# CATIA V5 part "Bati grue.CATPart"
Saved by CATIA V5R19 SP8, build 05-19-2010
Part number: Bati grue
Bounding box of the stored display mesh (mm): x -155 to 155, y -1230 to 420, z -1340 to 60
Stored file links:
  G:\EU_thinkMotion\CFAO_2010\MMS_groupe3\MMS_groupe3\rdalborgo\rdalborgo\Bati grue.CATPart
  G:\EU_thinkMotion\CFAO_2010\MMS_groupe3\MMS_groupe3\rdalborgo\rdalborgo\rdalborgo.CATProduct
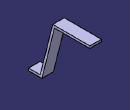
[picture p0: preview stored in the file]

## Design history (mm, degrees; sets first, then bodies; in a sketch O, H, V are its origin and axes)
External parameters (linked from other documents)
  External.entraxe = 500 mm
  `External.Largeur bielle` = 210 mm
Set1
  Plane1: linked copy from another document
  Point1 to Point3: linked copy from another document
  Plane2: linked copy from another document
  Plane3: linked copy from another document
Body1 (main body)
  Sketch1 on Plane1, origin (0, 0, 0), H (0, 1, 0), V (0, 0, 1)
    point P1 (-580, 60)
    line L1 (-580, 60) -> (420, 60)
    line L2 (420, 60) -> (420, 0)
    line L3 (420, 0) -> (-533.2139, 0)
    line L4 (-533.2139, 0) -> (-870, -1340)
    line L5 (-870, -1340) -> (-1230, -1340)
    line L6 (-1230, -1340) -> (-1230, -1280)
    line L7 (-1230, -1280) -> (-916.7861, -1280)
    line L8 (-916.7861, -1280) -> (-580, 60)
    point P9 (-580, 60)
    reference projected point E1 (320, 0) from Point1
    reference projected point E2 (320, 0) from Point1
    reference projected point E3 (-950, -1340) from Point3
    reference projected point E4 (-950, -1340) from Point3
    distance L3 L1 = 60
    distance L7 L5 = 60
    distance L8 L4 = 60
    distance L2 E1 = 100
    length L1 = 1000 {= External.entraxe +500mm}
    length L5 = 360
    distance L6 E4 = 280
    horizontal: L1 H, L3 H, L5 H, L7 H
    vertical: L2 V, L6 V
    coincidence: L3 E2, E3 L5, P1 P9
  Pad1: profile Sketch1, direction (1, 0, 0), length 155 {= `External.Largeur bielle` /2+50mm}, mirrored extent
  Sketch2 on face of Pad1 from Sketch1.L5, origin (-124.0653, -1194.0759, -1340), H (1, 0, 0), V (0, -1, 0)
    point P1 (174.0653, -64.0759)
    reference intersected line E1 through (124.0653, 0) direction (0, 1) from Plane1
    reference intersected line E2 through (0, -244.0759) direction (1, 0) from Plane2
    distance P1 E1 = 50
    distance P1 E2 = 180
  Hole1: placed by Sketch2, at (50, -1130, -1340) direction (0, 0, 1), diameter 10, depth 30
  RectPattern1: of Hole1, direction 1 instances 2, spacing 200, along face of Pad1 from Sketch1.L5 reversed, direction 2 instances 2, spacing 100, along face of Pad1 from Sketch1.L5
  Sketch3 on face of Pad1 from Sketch1.L3, origin (86.1973, -350.7932, 0), H (1, 0, 0), V (0, -1, 0)
    point P1 (-26.1973, -225.7932)
    reference intersected line E1 through (-86.1973, 0) direction (0, 1) from Plane1
    reference intersected line E2 through (0, -350.7932) direction (1, 0) from Plane3
    distance P1 E1 = 60
    distance P1 E2 = 125 {= External.entraxe /4}
  Hole2: placed by Sketch3, at (60, -125, 0) direction (0, 0, 1), diameter 20, depth 45
  RectPattern2: of Hole2, direction 1 instances 2, spacing 250 {= External.entraxe /2}, along face of Pad1 from Sketch1.L3 reversed, direction 2 instances 2, spacing 120, along face of Pad1 from Sketch1.L3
